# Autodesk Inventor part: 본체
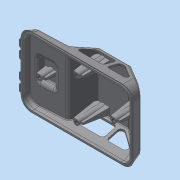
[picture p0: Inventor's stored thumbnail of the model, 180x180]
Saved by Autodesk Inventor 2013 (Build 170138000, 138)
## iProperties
Created: 2015-05
Part Number: 본체
Material: 일반
Document SubType Name: Modeling
Designer: Administrator
Density: 1 g/cm^3
Author: Administrator
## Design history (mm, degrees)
sketch "스케치1"
  geometry: L1 (-60, 0)-(60, 0); L2 (-60, 0)-(-60, 1); L3 (-60, 1)-(60, 1); L4 (60, 1)-(60, 0); L5 (60, 1)-(61, 1); L6 (61, 1)-(58.321, 11); L7 (58.321, 11)-(28.321, 31); L8 (-58.856, 9)-(-19, 11.089); L9 (-19, 11.089)-(-6.558, 31); L10 (-6.558, 31)-(28.321, 31); L11 (-58.856, 9)-(-61, 1); L12 (-61, 1)-(-60, 1); 3 further points
  constraints: 24 end point, 3 parallel, 3 perpendicular, 2 coincident, 2 midpoint, 1 horizontal
  dimensions: "d9" = 120 distance of L1.start L1.end; "d10" = 1 distance of L3.end L1.end; "d11" = 105 deg angle of L6 L1; "d13" = 30 horizontal distance of L6.end L7.end; "d14" = 20 vertical distance of L6.end L7.end; "d15" = 1 distance of L3.end L5.end; "d25" = 1 distance of L11.end L2.end; "d27" = 125 deg angle of L9 L8; "d28" = 3 deg angle of L3 L8; "d29" = 42 horizontal distance of L8.end L11.end; "d30" = 31 distance between parallel lines of L1 L10; "d31" = 9 vertical distance of L1.start L8.start; "d32" = 105 deg angle of L11 L1
extrude "돌출1" new body sketch "스케치1" stored distance "d33" = 76; taper "d34" = 0 deg
extrude "돌출2" join sketch "스케치1" stored distance "d35" = 74; taper "d36" = 0 deg
sketch "스케치3"
  geometry: L1 (1, 38)-(31, 29.962); L2 (1, -38)-(31, -29.962); L3 (31, -38)-(1, -38) reference; L4 (1, -38)-(1, -37) reference; L5 (1, -37)-(0, -37) reference; L6 (0, -37)-(0, 37) reference; L7 (0, 37)-(1, 37) reference; L8 (1, 37)-(1, 38) reference; L9 (1, 38)-(31, 38) reference; L10 (31, 38)-(31, -38) reference; 1 further point
  constraints: 4 end point, 2 point on line
  dimensions: "d41" = 105 deg angle of L2 L6
extrude "돌출4" cut sketch "스케치3" stored distance "d42" = 300; taper "d43" = 0 deg
fillet "모깎기5" dims "d72" = 12
fillet "모깎기6" dims "d73" = 12
fillet "모깎기7" dims "d74" = 3
fillet "모깎기8" dims "d75" = 3
feature "쉘2" dims "d76" = 2
sketch "스케치9"
  geometry: L1 (-36.17, 8.186)-(-36.17, 57.845) reference; L2 (-29.909, 46.016)-(-9.909, 46.016); L3 (-9.909, 46.016)-(-9.909, 20.016); L4 (-9.909, 20.016)-(-29.909, 20.016); L5 (-29.909, 20.016)-(-29.909, 46.016); L6 (-40.909, 59.424)-(-40.909, 6.607) reference; 3 further points
  constraints: 8 end point, 2 midpoint, 2 parallel, 1 horizontal, 1 horizontal alignment, 1 perpendicular
  dimensions: "d77" = 20 distance of L2.start L2.end; "d79" = 26 distance of L4.end L2.start; "d80" = 11 distance between parallel lines of L5 L6
extrude "돌출9" join sketch "스케치9" distance "d81" = 5; taper "d82" = -20 deg
fillet "모깎기9" dims "d83" = 3
fillet "모깎기10" dims "d84" = 3
fillet "모깎기11" dims "d85" = 3
sketch "스케치10"
  geometry: L1 (-60, 1)-(-61, 1) reference; L2 (-61, 1)-(-59.421, 6.895) reference; L3 (-56.68, 9.114)-(-52.525, 9.332) reference; L4 (-49.813, 11.451)-(-49.486, 12.521) reference; L5 (-46.774, 14.64)-(-34.632, 15.276) reference; L6 (-31.713, 13.453)-(-31.276, 12.422) reference; L7 (-28.357, 10.598)-(-20.56, 11.007) reference; L8 (-18.172, 12.413)-(-7.439, 29.59) reference; L9 (-4.895, 31)-(27.412, 31) reference; L10 (29.076, 30.496)-(57.38, 11.627) reference; L11 (58.613, 9.908)-(61, 1) reference; L12 (61, 1)-(60, 1) reference; L13 (60, 1)-(60, 0) reference; L14 (60, 0)-(58, 0) reference; L15 (58, 0)-(58, 3) reference; L16 (58, 3)-(58.394, 3) reference; L17 (58.394, 3)-(56.681, 9.39) reference; L18 (56.27, 9.963)-(27.967, 28.832) reference; L19 (27.412, 29)-(-4.895, 29) reference; L20 (-5.743, 28.53)-(-16.476, 11.353) reference; L21 (-20.455, 9.01)-(-56.575, 7.117) reference; L22 (-57.489, 6.377)-(-58.394, 3) reference; L23 (-58.394, 3)-(-58, 3) reference; L24 (-58, 3)-(-58, 0) reference; L25 (-58, 0)-(-60, 0) reference; L26 (-60, 0)-(-60, 1) reference; L27 (-13.16, 11)-(-3.787, 26); L28 (-3.787, 26)-(17.84, 26); L29 (17.84, 26)-(17.84, 11); L30 (17.84, 11)-(-13.16, 11); L31 (21.307, 26)-(26.807, 26); L32 (26.807, 26)-(49.307, 11); L33 (49.307, 11)-(21.307, 11); L34 (21.307, 11)-(21.307, 26); A1 r 3 centre (-56.523, 6.118) between (-56.68, 9.114) and (-59.421, 6.895) reference; A2 r 3 centre (-52.682, 12.328) between (-52.525, 9.332) and (-49.813, 11.451) reference; A3 r 3 centre (-46.617, 11.644) between (-46.774, 14.64) and (-49.486, 12.521) reference; A4 r 3 centre (-34.474, 12.281) between (-31.713, 13.453) and (-34.632, 15.276) reference; A5 r 3 centre (-28.514, 13.594) between (-31.276, 12.422) and (-28.357, 10.598) reference; A6 r 3 centre (-20.717, 14.003) between (-20.56, 11.007) and (-18.172, 12.413) reference; A7 r 3 centre (-4.895, 28) between (-4.895, 31) and (-7.439, 29.59) reference; A8 r 3 centre (27.412, 28) between (29.076, 30.496) and (27.412, 31) reference; A9 r 3 centre (55.715, 9.131) between (58.613, 9.908) and (57.38, 11.627) reference; A10 r 1 centre (55.715, 9.131) between (56.681, 9.39) and (56.27, 9.963) reference; A11 r 1 centre (27.412, 28) between (27.967, 28.832) and (27.412, 29) reference; A12 r 1 centre (-4.895, 28) between (-4.895, 29) and (-5.743, 28.53) reference; A13 r 5 centre (-20.717, 14.003) between (-20.455, 9.01) and (-16.476, 11.353) reference; A14 r 1 centre (-56.523, 6.118) between (-56.575, 7.117) and (-57.489, 6.377) reference; 1 further point
  constraints: 16 end point, 5 parallel, 3 perpendicular, 1 point on line
  dimensions: "d86" = 5 distance between parallel lines of L27 L8; "d87" = 5 distance between parallel lines of L28 L9; "d89" = 15 distance between parallel lines of L30 L28; "d90" = 31 distance of L29.end L27.start; "d91" = 5 distance between parallel lines of L10 L32; "d92" = 15 distance between parallel lines of L33 L31; "d93" = 28 distance of L32.end L33.end
extrude "돌출10" cut sketch "스케치10" stored distance "d94" = 300; taper "d95" = 0 deg
feature "쉘3" dims "d96" = 2
sketch "스케치13"
  geometry: L1 (65.895, 54.068)-(65.895, 1.251) reference; 2 further points
  constraints: 1 horizontal alignment, 1 other
  dimensions: "d103" = 50 distance from line of point (15.895, 27.66) L1
feature "엠보싱1" sketch "스케치13" dims "d104" = 0.5, "d105" = 0
fillet "모깎기12" dims "d117" = 3
fillet "모깎기13" dims "d118" = 3
sketch "스케치15"
  geometry: L1 (109, -63.409)-(109, -10.591) reference; C1 r 3 at (88, -37); C2 r 3 at (8, -37); C3 r 3 at (48, -15); C4 r 3 at (48, -59); 1 further point
  constraints: 4 centre point, 2 horizontal alignment, 1 vertical alignment
  dimensions: "d119" = 6 diameter of C1; "d120" = 6 diameter of C2; "d121" = 6 diameter of C3; "d122" = 6 diameter of C4; "d123" = 21 distance from line of L1 C1.centre; "d124" = 40 horizontal distance of C3.centre C1.centre; "d125" = 40 horizontal distance of C2.centre C3.centre; "d126" = 22 distance of point (48, -37) C3.centre; "d127" = 22 distance of C4.centre point (48, -37)
extrude "돌출13" join sketch "스케치15" stored distance "d128" = 300; taper "d129" = 2 deg
node "작업 평면4"
sketch "스케치16"
  geometry: L1 (-49.141, 15.732)-(49.141, 15.732) reference; L2 (60.732, 4.141)-(60.732, -48.141) reference; L3 (49.141, -59.732)-(-49.141, -59.732) reference; L4 (-60.732, -48.141)-(-60.732, 4.141) reference; L5 (48, 13)-(-48, 13) reference; L6 (-58, 3)-(-58, -47) reference; L7 (-48, -57)-(48, -57) reference; L8 (58, -47)-(58, 3) reference; L9 (-5, 1)-(5, 1); L10 (5, 1)-(5, -1); L11 (5, -1)-(-5, -1); L12 (-5, -1)-(-5, 1); L13 (-5, 1)-(5, -1); L14 (5, 1)-(-5, -1); C1 r 3.07 at (0, 0) reference; C2 r 3.07 at (40, -22) reference; C3 r 3.07 at (-40, -22) reference; C4 r 3.07 at (0, -44) reference; A1 r 10 centre (48, 3) between (58, 3) and (48, 13) reference; A2 r 10 centre (-48, 3) between (-48, 13) and (-58, 3) reference; A3 r 10 centre (-48, -47) between (-58, -47) and (-48, -57) reference; A4 r 10 centre (48, -47) between (48, -57) and (58, -47) reference; 5 further points; 4 other entities
  constraints: 12 end point, 2 midpoint, 2 parallel, 1 horizontal, 1 perpendicular, 4 other
  dimensions: "d131" = 2 distance of L9.end L10.end; "d133" = 10 distance of L9.start L9.end
extrude "돌출14" join sketch "스케치16" stored distance "d134" = 300; taper "d135" = 5 deg
sketch "스케치17"
  geometry: C1 r 3 at (0, 0) reference; 1 further point
node "작업 평면5"
sketch "스케치18"
  geometry: L1 (35, 23)-(37.098, 23) reference; L2 (45, 21)-(42.902, 21) reference; L3 (45, 23)-(45, 21) reference; L4 (42.902, 23)-(45, 23) reference; L5 (35, 21)-(35, 23) reference; L6 (37.098, 21)-(35, 21) reference; L7 (-9.141, 37.732)-(89.141, 37.732) reference; L8 (100.732, 26.141)-(100.732, -26.141) reference; L9 (89.141, -37.732)-(-9.141, -37.732) reference; L10 (-20.732, -26.141)-(-20.732, 26.141) reference; L11 (88, 35)-(-8, 35) reference; L12 (-18, 25)-(-18, -25) reference; L13 (-8, -35)-(88, -35) reference; L14 (98, -25)-(98, 25) reference; L15 (-5, 1)-(5, 1); L16 (5, 1)-(5, -1); L17 (5, -1)-(-5, -1); L18 (-5, -1)-(-5, 1); L19 (-5, 1)-(5, -1); L20 (5, 1)-(-5, -1); C1 r 3.07 at (80, 0) reference; C2 r 3.07 at (0, 0) reference; C3 r 3.07 at (40, -22) reference; A1 r 3.07 centre (40, 22) between (37.098, 23) and (37.098, 21) reference; A2 r 3.07 centre (40, 22) between (37.098, 21) and (42.902, 21) reference; A3 r 3.07 centre (40, 22) between (42.902, 21) and (42.902, 23) reference; A4 r 3.07 centre (40, 22) between (42.902, 23) and (37.098, 23) reference; A5 r 10 centre (88, 25) between (98, 25) and (88, 35) reference; A6 r 10 centre (-8, 25) between (-8, 35) and (-18, 25) reference; A7 r 10 centre (-8, -25) between (-18, -25) and (-8, -35) reference; A8 r 10 centre (88, -25) between (88, -35) and (98, -25) reference; 5 further points; 4 other entities
  constraints: 12 end point, 2 midpoint, 2 parallel, 1 horizontal, 1 perpendicular, 4 other
  dimensions: "d137" = 10 distance of L16.end L17.end; "d138" = 2 distance of L15.end L16.end
extrude "돌출15" join sketch "스케치18" stored distance "d139" = 300; taper "d140" = 5 deg
node "작업 평면6"
sketch "스케치19"
  geometry: L1 (-35, 21)-(-37.098, 21) reference; L2 (-42.902, 21)-(-45, 21) reference; L3 (-45, 21)-(-45, 23) reference; L4 (-45, 23)-(-42.902, 23) reference; L5 (-37.098, 23)-(-35, 23) reference; L6 (-35, 23)-(-35, 21) reference; L7 (-5, 45)-(-2.902, 45) reference; L8 (5, 43)-(2.902, 43) reference; L9 (5, 45)-(5, 43) reference; L10 (2.902, 45)-(5, 45) reference; L11 (-5, 43)-(-5, 45) reference; L12 (-2.902, 43)-(-5, 43) reference; L13 (-49.141, 59.732)-(49.141, 59.732) reference; L14 (60.732, 48.141)-(60.732, -4.141) reference; L15 (49.141, -15.732)-(-49.141, -15.732) reference; L16 (-60.732, -4.141)-(-60.732, 48.141) reference; L17 (48, 57)-(-48, 57) reference; L18 (-58, 47)-(-58, -3) reference; L19 (-48, -13)-(48, -13) reference; L20 (58, -3)-(58, 47) reference; L21 (-5, 1)-(5, 1); L22 (5, 1)-(5, -1); L23 (5, -1)-(-5, -1); L24 (-5, -1)-(-5, 1); L25 (-5, 1)-(5, -1); L26 (5, 1)-(-5, -1); C1 r 3.07 at (40, 22) reference; C2 r 3.07 at (0, 0) reference; A1 r 3.07 centre (-40, 22) between (-42.902, 21) and (-37.098, 21) reference; A2 r 3.07 centre (-40, 22) between (-37.098, 23) and (-42.902, 23) reference; A3 r 3.07 centre (-40, 22) between (-37.098, 21) and (-37.098, 23) reference; A4 r 3.07 centre (-40, 22) between (-42.902, 23) and (-42.902, 21) reference; A5 r 3.07 centre (0, 44) between (-2.902, 45) and (-2.902, 43) reference; A6 r 3.07 centre (0, 44) between (-2.902, 43) and (2.902, 43) reference; A7 r 3.07 centre (0, 44) between (2.902, 43) and (2.902, 45) reference; A8 r 3.07 centre (0, 44) between (2.902, 45) and (-2.902, 45) reference; A9 r 10 centre (48, 47) between (58, 47) and (48, 57) reference; A10 r 10 centre (-48, 47) between (-48, 57) and (-58, 47) reference; A11 r 10 centre (-48, -3) between (-58, -3) and (-48, -13) reference; A12 r 10 centre (48, -3) between (48, -13) and (58, -3) reference; 5 further points; 4 other entities
  constraints: 12 end point, 2 midpoint, 2 parallel, 1 horizontal, 1 perpendicular, 4 other
  dimensions: "d142" = 10 distance of L22.end L23.end; "d143" = 2 distance of L21.end L22.end
extrude "돌출16" join sketch "스케치19" stored distance "d144" = 300; taper "d145" = 5 deg
node "작업 평면7"
sketch "스케치20"
  geometry: L1 (-35, -23)-(-37.098, -23) reference; L2 (-42.902, -23)-(-45, -23) reference; L3 (-45, -23)-(-45, -21) reference; L4 (-45, -21)-(-42.902, -21) reference; L5 (-37.098, -21)-(-35, -21) reference; L6 (-35, -21)-(-35, -23) reference; L7 (-75, -1)-(-77.098, -1) reference; L8 (-82.902, -1)-(-85, -1) reference; L9 (-85, -1)-(-85, 1) reference; L10 (-85, 1)-(-82.902, 1) reference; L11 (-77.098, 1)-(-75, 1) reference; L12 (-75, 1)-(-75, -1) reference; L13 (-45, 23)-(-42.902, 23) reference; L14 (-35, 21)-(-37.098, 21) reference; L15 (-35, 23)-(-35, 21) reference; L16 (-37.098, 23)-(-35, 23) reference; L17 (-45, 21)-(-45, 23) reference; L18 (-42.902, 21)-(-45, 21) reference; L19 (-89.141, 37.732)-(9.141, 37.732) reference; L20 (20.732, 26.141)-(20.732, -26.141) reference; L21 (9.141, -37.732)-(-89.141, -37.732) reference; L22 (-100.732, -26.141)-(-100.732, 26.141) reference; L23 (8, 35)-(-88, 35) reference; L24 (-98, 25)-(-98, -25) reference; L25 (-88, -35)-(8, -35) reference; L26 (18, -25)-(18, 25) reference; L27 (-5, 1)-(5, 1); L28 (5, 1)-(5, -1); L29 (5, -1)-(-5, -1); L30 (-5, -1)-(-5, 1); L31 (-5, 1)-(5, -1); L32 (5, 1)-(-5, -1); C1 r 3.07 at (0, 0) reference; A1 r 3.07 centre (-40, -22) between (-42.902, -23) and (-37.098, -23) reference; A2 r 3.07 centre (-40, -22) between (-37.098, -21) and (-42.902, -21) reference; A3 r 3.07 centre (-40, -22) between (-37.098, -23) and (-37.098, -21) reference; A4 r 3.07 centre (-40, -22) between (-42.902, -21) and (-42.902, -23) reference; A5 r 3.07 centre (-80, 0) between (-82.902, -1) and (-77.098, -1) reference; A6 r 3.07 centre (-80, 0) between (-77.098, 1) and (-82.902, 1) reference; A7 r 3.07 centre (-80, 0) between (-77.098, -1) and (-77.098, 1) reference; A8 r 3.07 centre (-80, 0) between (-82.902, 1) and (-82.902, -1) reference; A9 r 3.07 centre (-40, 22) between (-42.902, 23) and (-42.902, 21) reference; A10 r 3.07 centre (-40, 22) between (-42.902, 21) and (-37.098, 21) reference; A11 r 3.07 centre (-40, 22) between (-37.098, 21) and (-37.098, 23) reference; A12 r 3.07 centre (-40, 22) between (-37.098, 23) and (-42.902, 23) reference; A13 r 10 centre (8, 25) between (18, 25) and (8, 35) reference; A14 r 10 centre (-88, 25) between (-88, 35) and (-98, 25) reference; A15 r 10 centre (-88, -25) between (-98, -25) and (-88, -35) reference; A16 r 10 centre (8, -25) between (8, -35) and (18, -25) reference; 5 further points; 4 other entities
  constraints: 12 end point, 2 midpoint, 2 parallel, 1 horizontal, 1 perpendicular, 4 other
  dimensions: "d147" = 10 distance of L28.end L29.end; "d148" = 2 distance of L27.end L28.end
extrude "돌출17" join sketch "스케치20" stored distance "d149" = 300; taper "d150" = 5 deg
sketch "스케치21"
  geometry: C1 r 3 at (0, 0) reference; C2 r 3 at (-40, -22) reference; C3 r 3 at (0, -44) reference; C4 r 3 at (40, -22) reference; 1 further point
hole "구멍1" sketch "스케치21" at (0, 0), (40, -22), (0, -44), (-40, -22) diameter "d151" = 3.242; stored, may be unused: countersink angle "d155" = 90 deg, drill point angle "d157" = 118 deg; dims "d152" = 9, "d153" = 4, "d154" = 2, "d156" = 11
node "작업 평면9"
  node "작업 평면8"
sketch "스케치22"
  geometry: A1 r 4 centre (-1, -21) between (-1, -17) and (-1, -25); A2 r 4 centre (-1, -10) between (-1, -6) and (-1, -14); A3 r 4 centre (-1, 10) between (-1, 14) and (-1, 6); A4 r 4 centre (-1, 21) between (-1, 25) and (-1, 17); 4 further points
  constraints: 8 point on circle, 4 centre point, 4 vertical alignment, 14 other
  dimensions: "d160" = 8 diameter of A1; "d161" = 8 diameter of A2; "d162" = 8 diameter of A3; "d163" = 8 diameter of A4; "d164" = 10 distance of A3.centre point (-1, 0); "d165" = 11 distance of A4.centre A3.centre; "d166" = 10 distance of A2.centre point (-1, 0); "d167" = 11 distance of A1.centre A2.centre
extrude "돌출18" join sketch "스케치22" stored distance "d168" = 10; taper "d169" = 0 deg
chamfer "모따기1" distance "d170" = 1; stored, may be unused: second distance "d171" = 2, angle "d172" = 45 deg
feature "쉘1" dims "d47" = 2
sketch "스케치5"
  geometry: L1 (-61, 1)-(-58.856, 9) reference; L2 (-58.856, 9)-(-19, 11.089) reference; L3 (-19, 11.089)-(-6.558, 31) reference; L4 (-6.558, 31)-(28.321, 31) reference; L5 (28.321, 31)-(58.321, 11) reference; L6 (58.321, 11)-(61, 1) reference; L7 (61, 1)-(60, 1) reference; L8 (60, 1)-(60, 0) reference; L9 (60, 0)-(59, 0) reference; L10 (59, 0)-(59, 1) reference; L11 (59, 1)-(58, 1) reference; L12 (58, 1)-(58, 3) reference; L13 (58, 3)-(58.394, 3) reference; L14 (58.394, 3)-(56.584, 9.754) reference; L15 (56.584, 9.754)-(27.715, 29) reference; L16 (27.715, 29)-(-5.449, 29) reference; L17 (-5.449, 29)-(-17.856, 9.146) reference; L18 (-17.856, 9.146)-(-57.301, 7.079) reference; L19 (-57.301, 7.079)-(-58.394, 3) reference; L20 (-58.394, 3)-(-58, 3) reference; L21 (-58, 3)-(-58, 1) reference; L22 (-58, 1)-(-59, 1) reference; L23 (-59, 1)-(-59, 0) reference; L24 (-59, 0)-(-60, 0) reference; L25 (-60, 0)-(-60, 1) reference; L26 (-60, 1)-(-61, 1) reference; L27 (-58.394, 3)-(-58.929, 1); L28 (58.394, 3)-(58.929, 1); 1 further point
  constraints: 4 end point, 2 collinear, 2 point on line
extrude "돌출5" cut sketch "스케치5" stored distance "d48" = 70; taper "d49" = 0 deg
node "솔리드1"
node "투영된 루프2"
node "투영된 루프3"
node "절단 모서리 투영1"
node "절단 모서리 투영3"
node "절단 모서리 투영5"
node "절단 모서리 투영6"
node "절단 모서리 투영7"
node "절단 모서리 투영8"
node "절단 모서리 투영9"
other parameters: "d130" = -2, "d136" = -2, "d141" = -2, "d146" = -2, "d158" = -61, "d159" = -2
